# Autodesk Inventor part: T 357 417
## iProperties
Created: 2005-12
Part Number: T 357 417
Material: 2.0401.26
Document SubType Name: Modeling
Designer: I.Baliuc
Manufacturer: Standard
Standards Organization: Custom
Description: Welle
Density: 8.2 g/cm^3
Title: Welle
Company: Mayer & Müller AG Schaltgeräte
HalbzeugNorm: DIN 1761
Zweck: Strombahn DC-Schalter
Abmessung: Vkt 20
Author: T.Messerschmitt
Revision Number: 357417
Keywords: 382076
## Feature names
1. Extrusion2
2. Bohrung_M8x15 [Hole]
3. Spiegeln1 [Mirror]
